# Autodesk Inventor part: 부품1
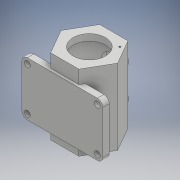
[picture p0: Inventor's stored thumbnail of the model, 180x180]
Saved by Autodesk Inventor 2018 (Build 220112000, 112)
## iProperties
Created: 2021-06
Part Number: 부품1
Material: Generic
Document SubType Name: Modeling
Designer: 1class19
Density: 1 g/cm^3
Appearance: Default
Author: 1class19
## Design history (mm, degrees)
sketch "스케치1"
  geometry: L1 (-52.5, 0)-(-26.25, 45.466); L2 (-26.25, 45.466)-(26.25, 45.466); L3 (26.25, 45.466)-(52.5, 0); L4 (52.5, 0)-(26.25, -45.466); L5 (26.25, -45.466)-(-26.25, -45.466); L6 (-26.25, -45.466)-(-52.5, 0); 2 further points
  constraints: 12 end point, 13 other
extrude "돌출1" new body sketch "스케치1" stored distance "d1" = 140; taper "d2" = 0 deg
node "작업 평면1"
sketch "스케치2"
  geometry: L1 (-52.5, 70)-(-52.5, 45); L2 (-52.5, -70)-(-52.5, -55); L3 (26.25, 70)-(-26.25, 70) reference; L4 (75, 45)-(-75, 45); L5 (75, 45)-(75, -55); L6 (75, -55)-(-75, -55); L7 (-75, -55)-(-75, 45); 1 further point
  constraints: 12 end point, 1 horizontal, 1 perpendicular
  dimensions: "d4" = 25 distance of L1.start L1.end; "d5" = 15 distance of L2.start L2.end; "d8" = 150 distance of L4.start L4.end; "d9" = 150 distance of L5.end L6.end
extrude "돌출2" join sketch "스케치2" distance "d10" = 12; taper "d11" = 0 deg
sketch "스케치3"
  geometry: L1 (26.25, 70)-(-26.25, 70) reference; L2 (0, 70)-(0, 30); L3 (0, 30)-(0, -30); C1 r 20 at (0, 30); C2 r 20 at (0, -30); 1 further point
  constraints: 4 end point, 2 centre point, 2 coincident, 1 midpoint, 1 point on line, 1 vertical
  dimensions: "d12" = 40 distance of L2.start L2.end; "d13" = 60 distance of L2.end L3.end; "d14" = 40 diameter of C1; "d15" = 40 diameter of C2
extrude "돌출3" join sketch "스케치3" distance "d16" = 52.5; taper "d17" = 0 deg
sketch "스케치4"
  geometry: C1 r 20 at (0, 60) reference; C2 r 15 at (0, 60); C3 r 15 at (0, 0); 1 further point
  constraints: 2 centre point, 1 coincident
  dimensions: "d18" = 30 diameter of C2; "d19" = 30 diameter of C3
extrude "돌출4" cut sketch "스케치4" distance "d20" = 8; taper "d21" = 0 deg
sketch "스케치5"
  geometry: C1 r 15 at (0, 60) reference; C2 r 12.5 at (0, 60); C3 r 12.5 at (0, 0); 1 further point
  constraints: 2 centre point, 1 coincident
  dimensions: "d23" = 25 diameter of C2; "d24" = 25 diameter of C3
extrude "돌출5" cut sketch "스케치5" distance "d25" = 30; taper "d26" = 0 deg
sketch "스케치6"
  geometry: C1 r 30 at (0, 0); 1 further point
  constraints: 1 centre point, 1 coincident
  dimensions: "d27" = 60 diameter of C1
extrude "돌출6" cut sketch "스케치6" distance "d28" = 12; taper "d29" = 0 deg
sketch "스케치7"
  geometry: C1 r 30 at (0, 0); 1 further point
  constraints: 1 centre point, 1 coincident
  dimensions: "d30" = 60 diameter of C1
extrude "돌출7" cut sketch "스케치7" distance "d31" = 12; taper "d32" = 0 deg
sketch "스케치8"
  geometry: C1 r 37.5 at (0, 0); 1 further point
  constraints: 1 centre point, 1 coincident
  dimensions: "d33" = 75 diameter of C1
extrude "돌출8" cut sketch "스케치8" distance "d34" = 116; taper "d35" = 0 deg
fillet "모깎기1" dims "d36" = 10
sketch "스케치9"
  geometry: C1 r 5.5 at (65, 45); C2 r 5.5 at (65, -35); C3 r 5.5 at (-65, 45); C4 r 5.5 at (-65, -35); A1 r 10 centre (65, 45) between (75, 45) and (65, 55) reference; A2 r 10 centre (65, -35) between (65, -45) and (75, -35) reference; A3 r 10 centre (-65, 45) between (-65, 55) and (-75, 45) reference; A4 r 10 centre (-65, -35) between (-75, -35) and (-65, -45) reference; 1 further point
  constraints: 4 centre point, 4 coincident
  dimensions: "d37" = 11 diameter of C1; "d38" = 11 diameter of C2; "d39" = 11 diameter of C3; "d40" = 11 diameter of C4
extrude "돌출9" cut sketch "스케치9" distance "d41" = 116; taper "d42" = 0 deg
sketch "스케치10" dims "d43" = 80
  geometry: L1 (0, 0)-(61.24, 61.24); L2 (0, 0)-(86.607, 0); 2 further points
  constraints: 4 end point, 1 coincident, 1 equal length, 1 horizontal, 1 point on line, 3 other
  dimensions: "d44" = 45 deg angle of L2 L1
hole "구멍1" sketch "스케치10" at (28.284, 28.284) diameter "d45" = 3.242; stored, may be unused: countersink angle "d49" = 90 deg, drill point angle "d51" = 118 deg; dims "d46" = 8, "d47" = 4, "d48" = 2, "d50" = 10
node "솔리드1"
